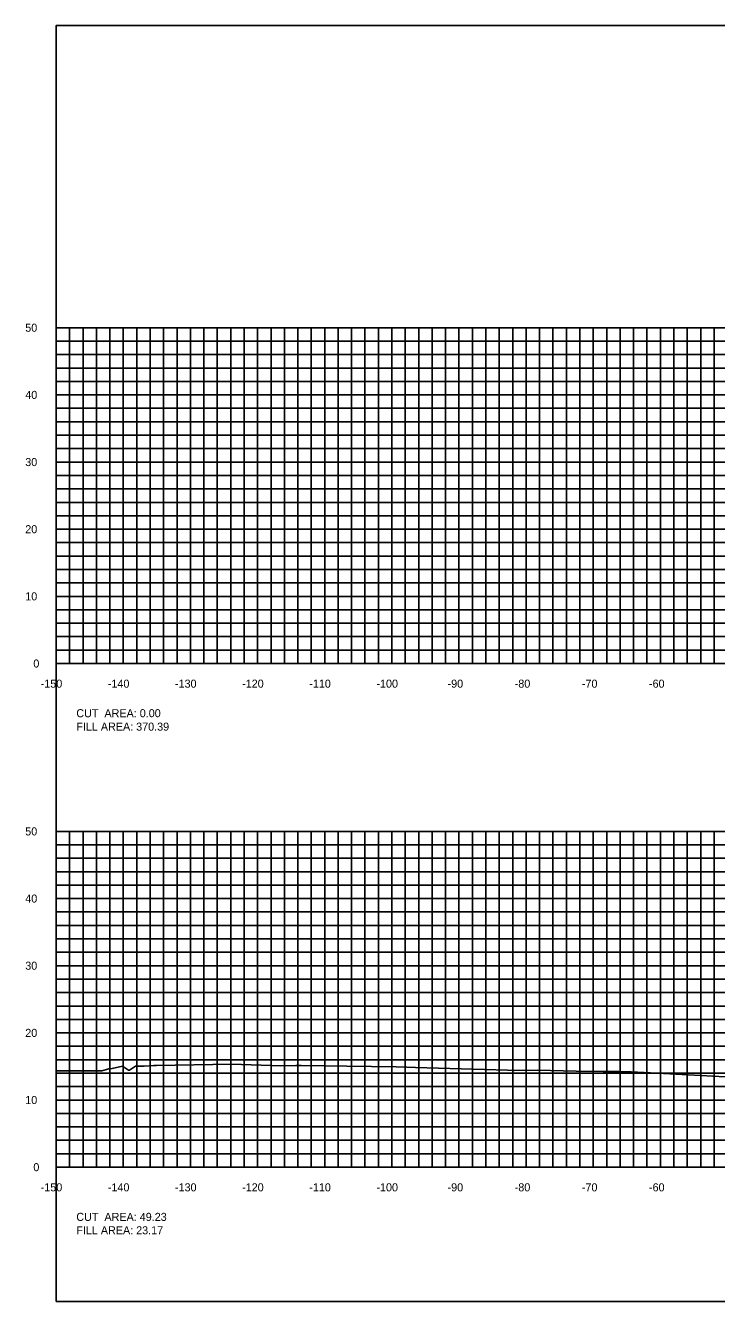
# Model space of a CAD drawing. Extents: x 1797714 to 1804825, y 249015 to 250269.
# Drawn here: x 1802476.4 to 1802579.4, y 250079.4 to 250269.4 of the extents above; entities that cross this region are included whole.
import ezdxf

# ---------------------------------------------------------------- set-up
doc = ezdxf.new("R2010")
doc.units = 0
for name, color, linetype in [('10', 7, 'Continuous'), ('31', 7, 'Continuous'), ('60', 7, 'Continuous'), ('ANNO-TXT', 7, 'Continuous'), ('Level 62', 7, 'Continuous'), ('M-ROADS', 7, 'Continuous')]:
    doc.layers.add(name, color=color, linetype=linetype)

msp = doc.modelspace()

# ---------------------------------------------------------------- linework, layer by layer
msp.add_lwpolyline([(1802481, 250079.43), (1802781, 250079.43), (1802781, 250269.43), (1802481, 250269.43)], close=True)
at = {"layer": '60'}
for p, q in [((1802480.94, 250224.43), (1802481, 250224.43)), ((1802481, 250174.43), (1802481, 250224.43)), ((1802480.94, 250214.43), (1802481, 250214.43)), ((1802480.94, 250204.43), (1802481, 250204.43)), ((1802480.94, 250194.43), (1802481, 250194.43)), ((1802480.94, 250184.43), (1802481, 250184.43)), ((1802480.94, 250174.43), (1802481, 250174.43)), ((1802481, 250174.43), (1802781, 250174.43)), ((1802481, 250174.37), (1802481, 250174.43)), ((1802491, 250174.37), (1802491, 250174.43)), ((1802501, 250174.37), (1802501, 250174.43)), ((1802511, 250174.37), (1802511, 250174.43)), ((1802521, 250174.37), (1802521, 250174.43)), ((1802531, 250174.37), (1802531, 250174.43)), ((1802541, 250174.37), (1802541, 250174.43)), ((1802551, 250174.37), (1802551, 250174.43)), ((1802561, 250174.37), (1802561, 250174.43)), ((1802571, 250174.37), (1802571, 250174.43)), ((1802480.94, 250149.43), (1802481, 250149.43)), ((1802481, 250099.43), (1802481, 250149.43)), ((1802480.94, 250139.43), (1802481, 250139.43)), ((1802480.94, 250129.43), (1802481, 250129.43)), ((1802480.94, 250119.43), (1802481, 250119.43)), ((1802480.94, 250109.43), (1802481, 250109.43)), ((1802480.94, 250099.43), (1802481, 250099.43)), ((1802481, 250099.43), (1802781, 250099.43)), ((1802481, 250099.37), (1802481, 250099.43)), ((1802491, 250099.37), (1802491, 250099.43)), ((1802501, 250099.37), (1802501, 250099.43)), ((1802511, 250099.37), (1802511, 250099.43)), ((1802521, 250099.37), (1802521, 250099.43)), ((1802531, 250099.37), (1802531, 250099.43)), ((1802541, 250099.37), (1802541, 250099.43)), ((1802551, 250099.37), (1802551, 250099.43)), ((1802561, 250099.37), (1802561, 250099.43)), ((1802571, 250099.37), (1802571, 250099.43))]:
    msp.add_line(p, q, dxfattribs=at)
at = {"layer": 'Level 62'}
for p, q in [((1802481, 250224.43), (1802781, 250224.43)), ((1802481, 250174.43), (1802481, 250224.43)), ((1802483, 250174.43), (1802483, 250224.43)), ((1802485, 250174.43), (1802485, 250224.43)), ((1802487, 250174.43), (1802487, 250224.43)), ((1802489, 250174.43), (1802489, 250224.43)), ((1802491, 250174.43), (1802491, 250224.43)), ((1802493, 250174.43), (1802493, 250224.43)), ((1802495, 250174.43), (1802495, 250224.43)), ((1802497, 250174.43), (1802497, 250224.43)), ((1802499, 250174.43), (1802499, 250224.43)), ((1802501, 250174.43), (1802501, 250224.43)), ((1802503, 250174.43), (1802503, 250224.43)), ((1802505, 250174.43), (1802505, 250224.43)), ((1802507, 250174.43), (1802507, 250224.43)), ((1802509, 250174.43), (1802509, 250224.43)), ((1802511, 250174.43), (1802511, 250224.43)), ((1802513, 250174.43), (1802513, 250224.43)), ((1802515, 250174.43), (1802515, 250224.43)), ((1802517, 250174.43), (1802517, 250224.43)), ((1802519, 250174.43), (1802519, 250224.43)), ((1802521, 250174.43), (1802521, 250224.43)), ((1802523, 250174.43), (1802523, 250224.43)), ((1802525, 250174.43), (1802525, 250224.43)), ((1802527, 250174.43), (1802527, 250224.43)), ((1802529, 250174.43), (1802529, 250224.43)), ((1802531, 250174.43), (1802531, 250224.43)), ((1802533, 250174.43), (1802533, 250224.43)), ((1802535, 250174.43), (1802535, 250224.43)), ((1802537, 250174.43), (1802537, 250224.43)), ((1802539, 250174.43), (1802539, 250224.43)), ((1802541, 250174.43), (1802541, 250224.43)), ((1802543, 250174.43), (1802543, 250224.43)), ((1802545, 250174.43), (1802545, 250224.43)), ((1802547, 250174.43), (1802547, 250224.43)), ((1802549, 250174.43), (1802549, 250224.43)), ((1802551, 250174.43), (1802551, 250224.43)), ((1802553, 250174.43), (1802553, 250224.43)), ((1802555, 250174.43), (1802555, 250224.43)), ((1802557, 250174.43), (1802557, 250224.43)), ((1802559, 250174.43), (1802559, 250224.43)), ((1802561, 250174.43), (1802561, 250224.43)), ((1802563, 250174.43), (1802563, 250224.43)), ((1802565, 250174.43), (1802565, 250224.43)), ((1802567, 250174.43), (1802567, 250224.43)), ((1802569, 250174.43), (1802569, 250224.43)), ((1802571, 250174.43), (1802571, 250224.43)), ((1802573, 250174.43), (1802573, 250224.43)), ((1802575, 250174.43), (1802575, 250224.43)), ((1802577, 250174.43), (1802577, 250224.43)), ((1802579, 250174.43), (1802579, 250224.43)), ((1802481, 250222.43), (1802781, 250222.43)), ((1802481, 250220.43), (1802781, 250220.43)), ((1802481, 250218.43), (1802781, 250218.43)), ((1802481, 250216.43), (1802781, 250216.43)), ((1802481, 250214.43), (1802781, 250214.43)), ((1802481, 250212.43), (1802781, 250212.43)), ((1802481, 250210.43), (1802781, 250210.43)), ((1802481, 250208.43), (1802781, 250208.43)), ((1802481, 250206.43), (1802781, 250206.43)), ((1802481, 250204.43), (1802781, 250204.43)), ((1802481, 250202.43), (1802781, 250202.43)), ((1802481, 250200.43), (1802781, 250200.43)), ((1802481, 250198.43), (1802781, 250198.43)), ((1802481, 250196.43), (1802781, 250196.43)), ((1802481, 250194.43), (1802781, 250194.43)), ((1802481, 250192.43), (1802781, 250192.43)), ((1802481, 250190.43), (1802781, 250190.43)), ((1802481, 250188.43), (1802781, 250188.43)), ((1802481, 250186.43), (1802781, 250186.43)), ((1802481, 250184.43), (1802781, 250184.43)), ((1802481, 250182.43), (1802781, 250182.43)), ((1802481, 250180.43), (1802781, 250180.43)), ((1802481, 250178.43), (1802781, 250178.43)), ((1802481, 250176.43), (1802781, 250176.43)), ((1802481, 250174.43), (1802781, 250174.43)), ((1802481, 250149.43), (1802781, 250149.43)), ((1802481, 250099.43), (1802481, 250149.43)), ((1802483, 250099.43), (1802483, 250149.43)), ((1802485, 250099.43), (1802485, 250149.43)), ((1802487, 250099.43), (1802487, 250149.43)), ((1802489, 250099.43), (1802489, 250149.43)), ((1802491, 250099.43), (1802491, 250149.43)), ((1802493, 250099.43), (1802493, 250149.43)), ((1802495, 250099.43), (1802495, 250149.43)), ((1802497, 250099.43), (1802497, 250149.43)), ((1802499, 250099.43), (1802499, 250149.43)), ((1802501, 250099.43), (1802501, 250149.43)), ((1802503, 250099.43), (1802503, 250149.43)), ((1802505, 250099.43), (1802505, 250149.43)), ((1802507, 250099.43), (1802507, 250149.43)), ((1802509, 250099.43), (1802509, 250149.43)), ((1802511, 250099.43), (1802511, 250149.43)), ((1802513, 250099.43), (1802513, 250149.43)), ((1802515, 250099.43), (1802515, 250149.43)), ((1802517, 250099.43), (1802517, 250149.43)), ((1802519, 250099.43), (1802519, 250149.43)), ((1802521, 250099.43), (1802521, 250149.43)), ((1802523, 250099.43), (1802523, 250149.43)), ((1802525, 250099.43), (1802525, 250149.43)), ((1802527, 250099.43), (1802527, 250149.43)), ((1802529, 250099.43), (1802529, 250149.43)), ((1802531, 250099.43), (1802531, 250149.43)), ((1802533, 250099.43), (1802533, 250149.43)), ((1802535, 250099.43), (1802535, 250149.43)), ((1802537, 250099.43), (1802537, 250149.43)), ((1802539, 250099.43), (1802539, 250149.43)), ((1802541, 250099.43), (1802541, 250149.43)), ((1802543, 250099.43), (1802543, 250149.43)), ((1802545, 250099.43), (1802545, 250149.43)), ((1802547, 250099.43), (1802547, 250149.43)), ((1802549, 250099.43), (1802549, 250149.43)), ((1802551, 250099.43), (1802551, 250149.43)), ((1802553, 250099.43), (1802553, 250149.43)), ((1802555, 250099.43), (1802555, 250149.43)), ((1802557, 250099.43), (1802557, 250149.43)), ((1802559, 250099.43), (1802559, 250149.43)), ((1802561, 250099.43), (1802561, 250149.43)), ((1802563, 250099.43), (1802563, 250149.43)), ((1802565, 250099.43), (1802565, 250149.43)), ((1802567, 250099.43), (1802567, 250149.43)), ((1802569, 250099.43), (1802569, 250149.43)), ((1802571, 250099.43), (1802571, 250149.43)), ((1802573, 250099.43), (1802573, 250149.43)), ((1802575, 250099.43), (1802575, 250149.43)), ((1802577, 250099.43), (1802577, 250149.43)), ((1802579, 250099.43), (1802579, 250149.43)), ((1802481, 250147.43), (1802781, 250147.43)), ((1802481, 250145.43), (1802781, 250145.43)), ((1802481, 250143.43), (1802781, 250143.43)), ((1802481, 250141.43), (1802781, 250141.43)), ((1802481, 250139.43), (1802781, 250139.43)), ((1802481, 250137.43), (1802781, 250137.43)), ((1802481, 250135.43), (1802781, 250135.43)), ((1802481, 250133.43), (1802781, 250133.43)), ((1802481, 250131.43), (1802781, 250131.43)), ((1802481, 250129.43), (1802781, 250129.43)), ((1802481, 250127.43), (1802781, 250127.43)), ((1802481, 250125.43), (1802781, 250125.43)), ((1802481, 250123.43), (1802781, 250123.43)), ((1802481, 250121.43), (1802781, 250121.43)), ((1802481, 250119.43), (1802781, 250119.43)), ((1802481, 250117.43), (1802781, 250117.43)), ((1802481, 250115.43), (1802781, 250115.43)), ((1802481, 250113.43), (1802781, 250113.43)), ((1802481, 250111.43), (1802781, 250111.43)), ((1802481, 250109.43), (1802781, 250109.43)), ((1802481, 250107.43), (1802781, 250107.43)), ((1802481, 250105.43), (1802781, 250105.43)), ((1802481, 250103.43), (1802781, 250103.43)), ((1802481, 250101.43), (1802781, 250101.43)), ((1802481, 250099.43), (1802781, 250099.43))]:
    msp.add_line(p, q, dxfattribs=at)
at = {"layer": 'M-ROADS'}
msp.add_lwpolyline([(1802481, 250113.78), (1802484.12, 250113.77), (1802484.5, 250113.77), (1802484.92, 250113.77), (1802485.89, 250113.77), (1802486.73, 250113.77), (1802487.22, 250113.77), (1802487.78, 250113.77), (1802488.83, 250114.06), (1802489.34, 250114.13), (1802490.88, 250114.47), (1802491.79, 250113.87), (1802491.94, 250113.87), (1802492.82, 250114.49), (1802493.57, 250114.46), (1802494.09, 250114.49), (1802495.55, 250114.59), (1802495.97, 250114.56), (1802507.12, 250114.78), (1802514.44, 250114.52), (1802516.68, 250114.56), (1802517.49, 250114.58), (1802524.28, 250114.46), (1802531.65, 250114.36), (1802533.21, 250114.3), (1802534.54, 250114.25), (1802548.2, 250113.87), (1802549.09, 250113.85), (1802549.22, 250113.85), (1802552.67, 250113.87), (1802558.46, 250113.72), (1802562.46, 250113.67), (1802563.81, 250113.67), (1802564.82, 250113.67), (1802566.64, 250113.62), (1802571.46, 250113.37), (1802580.63, 250112.87)], dxfattribs=at)

# ---------------------------------------------------------------- texts
at = {"layer": '10'}
for s, p in [('-150', (1802478.7, 250170.83)), ('-140', (1802488.7, 250170.83)), ('-130', (1802498.7, 250170.83)), ('-120', (1802508.7, 250170.83)), ('-110', (1802518.7, 250170.83)), ('-100', (1802528.7, 250170.83)), ('-90', (1802539.3, 250170.83)), ('-80', (1802549.3, 250170.83)), ('-70', (1802559.3, 250170.83)), ('-60', (1802569.3, 250170.83)), ('-150', (1802478.7, 250095.83)), ('-140', (1802488.7, 250095.83)), ('-130', (1802498.7, 250095.83)), ('-120', (1802508.7, 250095.83)), ('-110', (1802518.7, 250095.83)), ('-100', (1802528.7, 250095.83)), ('-90', (1802539.3, 250095.83)), ('-80', (1802549.3, 250095.83)), ('-70', (1802559.3, 250095.83)), ('-60', (1802569.3, 250095.83))]:
    msp.add_text(s, height=1.2, dxfattribs=at).set_placement(p)
at = {"layer": '31'}
for s, p in [('50', (1802476.4, 250223.83)), ('40', (1802476.4, 250213.83)), ('30', (1802476.4, 250203.83)), ('20', (1802476.4, 250193.83)), ('10', (1802476.4, 250183.83)), ('0', (1802477.6, 250173.83)), ('50', (1802476.4, 250148.83)), ('40', (1802476.4, 250138.83)), ('30', (1802476.4, 250128.83)), ('20', (1802476.4, 250118.83)), ('10', (1802476.4, 250108.83)), ('0', (1802477.6, 250098.83))]:
    msp.add_text(s, height=1.2, dxfattribs=at).set_placement(p)
at = {"layer": '60'}
for p in [(1802481, 250174.43), (1802481, 250099.43)]:
    msp.add_text('-', height=0.0001, dxfattribs=at).set_placement(p)
at = {"layer": 'ANNO-TXT'}
for s, p in [('CUT  AREA: 0.00', (1802484, 250166.43)), ('FILL AREA: 370.39', (1802484, 250164.43)), ('CUT  AREA: 49.23', (1802484, 250091.43)), ('FILL AREA: 23.17', (1802484, 250089.43))]:
    msp.add_text(s, height=1.2, dxfattribs=at).set_placement(p)

doc.saveas('drawing.dxf')
